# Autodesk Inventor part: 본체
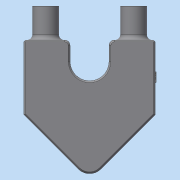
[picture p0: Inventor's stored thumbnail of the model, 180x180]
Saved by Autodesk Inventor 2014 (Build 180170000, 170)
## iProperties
Created: 2025-02
Part Number: 본체
Material: 일반
Document SubType Name: Modeling
Designer: dg
Density: 1 g/cm^3
Appearance: 기본값
Author: dg
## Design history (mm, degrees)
sketch "스케치1"
  geometry: L1 (-37, 21)-(37, 21); L2 (37, 21)-(37, -21); L3 (37, -21)-(-37, -21); L4 (-37, -21)-(-37, 21); L5 (-37, -21)-(0, -58); L6 (0, -58)-(37, -21); 3 further points
  constraints: 12 end point, 2 midpoint, 2 parallel, 2 vertical alignment, 1 horizontal, 1 horizontal alignment, 1 perpendicular
  dimensions: "d0" = 90 deg angle of L6 L5; "d1" = 42 distance of L3.end L1.start; "d2" = 74 distance of L1.start L1.end
extrude "돌출1" new body sketch "스케치1" distance "d3" = 74; taper "d4" = 0 deg
node "작업 평면1"
sketch "스케치2"
  geometry: L1 (0, -58)-(-37, -21) reference; L2 (37, -21)-(0, -58) reference; L3 (-37, -21)-(-37, 21) reference; L4 (37, 21)-(37, -21) reference; L5 (-37, -18)-(0, -55); L6 (0, -55)-(37, -18); 1 further point
  constraints: 4 end point, 2 perpendicular, 2 point on line
  dimensions: "d5" = 90 deg angle of L6 L5; "d6" = 3 distance of L1.end L5.start
extrude "돌출2" cut sketch "스케치2" stored distance "d7" = 36; taper "d8" = 0 deg
sketch "스케치3"
  geometry: L1 (37, 21)-(-37, 21) reference; L2 (-11, 9)-(-11, 21); L3 (11, 9)-(11, 21); A1 r 11 centre (0, 9) between (-11, 9) and (11, 9); 1 further point
  constraints: 4 end point, 2 perpendicular, 2 point on circle, 2 point on line, 2 tangent, 1 centre point, 1 vertical alignment
  dimensions: "d9" = 22 diameter of A1; "d10" = 12 distance from line of L1 A1.centre
extrude "돌출3" cut sketch "스케치3" stored distance "d11" = 36; taper "d12" = 0 deg
sketch "스케치4"
  geometry: L1 (0, -55)-(-37, -18) reference; L2 (-37, -18)-(-37, 21) reference; L3 (-37, 21)-(-11, 21) reference; L4 (-11, 21)-(-11, 9) reference; L5 (11, 9)-(11, 21) reference; L6 (11, 21)-(37, 21) reference; L7 (37, 21)-(37, -18) reference; L8 (37, -18)-(0, -55) reference; L9 (-37, 7)-(-23, 21); L10 (23, 21)-(37, 7); A1 r 11 centre (0, 9) between (-11, 9) and (11, 9) reference; 1 further point
  constraints: 4 end point, 4 point on line, 1 parallel, 1 perpendicular
  dimensions: "d13" = 14 distance from line of L3 L9.start; "d14" = 14 distance of L10.end L6.end
extrude "돌출4" cut sketch "스케치4" stored distance "d15" = 20; taper "d16" = 0 deg
sketch "스케치5"
  geometry: L1 (-19.799, 0)-(-19.799, 20) reference; C1 r 6.5 at (-9.899, 10); 3 further points
  constraints: 1 centre point, 1 horizontal alignment, 1 midpoint, 1 vertical alignment
  dimensions: "d17" = 13 diameter of C1
extrude "돌출5" cut sketch "스케치5" distance "d18" = 3; taper "d19" = 0 deg
sketch "스케치6"
  geometry: L1 (12, -47)-(12, -27) reference; C1 r 21 at (-11, -37); 2 further points
  constraints: 1 centre point, 1 horizontal alignment, 1 midpoint, 1 vertical alignment
  dimensions: "d20" = 42 diameter of C1
extrude "돌출6" cut sketch "스케치6" distance "d21" = 8; taper "d22" = 0 deg
hole "구멍1" diameter "d25" = 32; stored, may be unused: countersink angle "d29" = 90 deg, drill point angle "d31" = 0 deg; dims "d23" = 10, "d24" = 10, "d26" = 6, "d27" = 4, "d28" = 2, "d30" = 20
hole "구멍2" diameter "d34" = 8; stored, may be unused: countersink angle "d38" = 90 deg, drill point angle "d40" = 0 deg; dims "d32" = 10, "d33" = 10, "d35" = 6, "d36" = 4, "d37" = 2, "d39" = 20
sketch "스케치7"
  geometry: L1 (-11, -37)-(10, -37); L2 (-35.749, -61.749)-(13.749, -12.251); C1 r 7.5 at (13.749, -12.251); C2 r 7.5 at (-35.749, -61.749); A1 r 21 centre (-11, -37) between (0, -54.889) and (0, -19.111) reference; A2 r 35 centre (-11, -37) between (13.749, -12.251) and (-35.749, -61.749); 1 further point
  constraints: 4 end point, 3 centre point, 3 coincident, 3 point on circle, 1 midpoint
  dimensions: "d42" = 70 diameter of A2; "d43" = 45 deg angle of L1 L2; "d44" = 15 diameter of C1; "d45" = 15 diameter of C2
extrude "돌출7" join sketch "스케치7" distance "d46" = 19; taper "d47" = 0 deg
hole "구멍3" diameter "d50" = 4.917; stored, may be unused: countersink angle "d54" = 90 deg, drill point angle "d56" = 118 deg; dims "d48" = 10, "d49" = 10, "d51" = 12, "d52" = 4, "d53" = 2, "d55" = 14
hole "구멍4" diameter "d59" = 4.917; stored, may be unused: countersink angle "d63" = 90 deg, drill point angle "d65" = 118 deg; dims "d57" = 10, "d58" = 10, "d60" = 12, "d61" = 4, "d62" = 2, "d64" = 14
chamfer "모따기1" distance "d66" = 1; stored, may be unused: second distance "d67" = 2, angle "d68" = 45 deg
fillet "모깎기1" dims "d69" = 6
fillet "모깎기2" dims "d70" = 9
chamfer "모따기2" distance "d71" = 1; stored, may be unused: second distance "d72" = 2, angle "d73" = 45 deg
chamfer "모따기3" distance "d74" = 1; stored, may be unused: second distance "d75" = 2, angle "d76" = 45 deg
fillet "모깎기3" dims "d77" = 3
fillet "모깎기4" dims "d78" = 3
chamfer "모따기4" distance "d79" = 1; stored, may be unused: second distance "d80" = 2, angle "d81" = 45 deg
chamfer "모따기5" distance "d82" = 1; stored, may be unused: second distance "d83" = 2, angle "d84" = 45 deg
fillet "모깎기5" dims "d85" = 3
chamfer "모따기6" distance "d86" = 1; stored, may be unused: second distance "d87" = 2, angle "d88" = 45 deg
chamfer "모따기7" distance "d89" = 1; stored, may be unused: second distance "d90" = 2, angle "d91" = 45 deg
sketch "스케치8"
  geometry: L1 (28, 25)-(8, 25) reference; L2 (50.249, 58)-(35.249, 58) reference; 3 further points
  constraints: 1 midpoint, 1 vertical alignment, 1 other
  dimensions: "d92" = 40 distance from line of point (18, 18) L2
feature "엠보싱1" sketch "스케치8" dims "d0" = 90 deg, "d1" = 42, "d2" = 74, "d7" = 36, "d93" = 0.5, "d94" = 0
chamfer "모따기8" distance "d95" = 1; stored, may be unused: second distance "d96" = 2, angle "d97" = 45 deg
chamfer "모따기9" distance "d98" = 1; stored, may be unused: second distance "d99" = 2, angle "d100" = 45 deg
node "솔리드1"
mirror "대칭1"
node "절단 모서리 투영1"
